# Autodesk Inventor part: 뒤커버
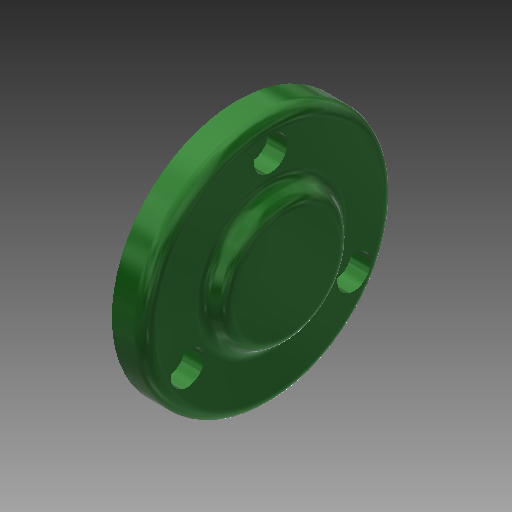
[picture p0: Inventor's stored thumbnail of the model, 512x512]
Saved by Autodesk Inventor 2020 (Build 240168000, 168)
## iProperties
Created: 2015-11
Part Number: 뒤커버
Material: 알루미늄 6061
Document SubType Name: Modeling
Designer: mduedu
Density: 1 g/cm^3
Appearance: 매끄러움 - 짙은 산림 녹색
Author: mduedu
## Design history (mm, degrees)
sketch "스케치5"
  geometry: C1 r 30 at (0, 0); 2 further points
  constraints: 2 coincident, 1 centre point
  dimensions: "d66" = 60 diameter of C1
extrude "돌출2" new body sketch "스케치5" distance "d67" = 8; taper "d68" = 0 deg
sketch "스케치8"
  geometry: C1 r 16.5 at (0, 0); 1 further point
  constraints: 1 centre point, 1 coincident
  dimensions: "d98" = 33 diameter of C1
extrude "돌출4" join sketch "스케치8" distance "d99" = 4; taper "d100" = -30 deg
sketch "스케치6"
  geometry: C1 r 16 at (0, 0); 1 further point
  constraints: 1 centre point, 1 coincident
  dimensions: "d69" = 32 diameter of C1
extrude "돌출3" join sketch "스케치6" distance "d70" = 3; taper "d71" = 0 deg
hole "구멍5" diameter "d74" = 25; stored, may be unused: countersink angle "d78" = 90 deg, drill point angle "d80" = 0 deg; dims "d72" = 10, "d73" = 10, "d75" = 6, "d76" = 4, "d77" = 2, "d79" = 10
fillet "모깎기8" dims "d82" = 3
fillet "모깎기9" dims "d83" = 3
fillet "모깎기10" dims "d84" = 0.3
sketch "스케치7" dims "d85" = 46
  geometry: 3 further points
  constraints: 2 vertical alignment, 1 coincident, 2 other
hole "구멍6" sketch "스케치7" at (0, 23) diameter "d86" = 4.5; stored, may be unused: countersink angle "d90" = 90 deg, drill point angle "d92" = 0 deg; dims "d87" = 6, "d88" = 8, "d89" = 4.6, "d91" = 10
chamfer "모따기2" distance "d102" = 1; stored, may be unused: second distance "d103" = 2, angle "d104" = 45 deg
node "솔리드2"
pattern_circular "원형 패턴3" dims angle "d94" = 360 deg
